(* Logix 5000 project; controller ANG1E_AOI_sample_RSLogix_V31 vendor 1 type 14 code 108 rev 31.11; software revision 31.02 *)

TASK MainTask (continuous, watchdog 500 ms) : MainProgram

MODULES
   Local : vendor 1 type 14 code 108 (Compact 0, rev 31.11)
      AMCI_ANG1E : ETHERNET-MODULE (Ethernet 192.168.0.50, rev 1.1, Output RPI 10 ms)
END_MODULES

TYPE ANG1_Driver_Command :
STRUCT
   Absolute_move : BOOL;
   Relative_move : BOOL;
   Hold_move : BOOL;
   Resume_move : BOOL;
   Immediate_stop : BOOL;
   Find_Home_CW : BOOL;
   Find_Home_CCW : BOOL;
   CW_Manual_Move : BOOL;
   CCW_Manual_Move : BOOL;
   Preset_Motor_Position : BOOL;
   Reset_Errors : BOOL;
   Program_Assembled_Move : BOOL;
   Program_Assembled_Move_segments : BOOL;
   Run_Assembled_Move : BOOL;
   Preset_Encoder : BOOL;
   Mode_bit : BOOL;   // "0"=command mode, "1" = configuraiton mode
   Motor_Current_Key0 : BOOL;
   Motor_Current_Key1 : BOOL;
   Encoder_move : BOOL;
   Reserved_bit_3 : BOOL;
   Blend_Move_Direction : BOOL;
   Reserved_bit_5 : BOOL;
   Enable_Electronic_Gearing : BOOL;
   Reserved_bit_7 : BOOL;
   Reserved_bit_8 : BOOL;
   Reserved_bit_9 : BOOL;
   Reserved_bit_10 : BOOL;
   Home_Proximity_Bit : BOOL;
   Reserved_bit_12 : BOOL;
   General_Purpose_output : BOOL;
   Reserved_bit_14 : BOOL;
   Drive_Enable : BOOL;   // "0" to disable motor current, "1" to enable motor current
   upper_target_position : INT;
   lower_target_position : INT;
   upper_programmed_speed : INT;
   lower_programmed_speed : INT;
   Acceleration : INT;   // 1 to 5000 steps/ms/sec
   Decleration : INT;   // 1 to 5000 steps/ms/sec
   Motor_Current : INT;   // 10 to 40, represents 1.0 to 4.0 amps rms
   acceleration_jerk : INT;   // 0 to 5000
END_STRUCT
END_TYPE

TYPE ANG1_Driver_Configuration :
STRUCT
   Input_1_bit_0 : BOOL;
   Input_1_bit_1 : BOOL;
   Input_1_bit_2 : BOOL;
   Input_2_bit_3 : BOOL;
   Input_2_bit_4 : BOOL;
   Input_2_bit_5 : BOOL;
   Input_3_bit_6 : BOOL;
   Input_3_bit_7 : BOOL;
   Input_3_bit_8 : BOOL;
   Reserved_bit_9 : BOOL;
   Quad_encoder_enable : BOOL;   // "0" when Quadrature Encoder is not used, "1" when Quadrature is used
   Home_Proximity_enable : BOOL;   // "0" when the Home Proximity bit is not used, "1" when the Home Proximity will be used
   Reserved_bit_12 : BOOL;
   Stall_detection_enable : BOOL;   // "0' disables Stall Detection, "1" enables Stall Detection
   Anti_resonance_enable : BOOL;   // "0" Enables Antiresonance, "1" Disables Antiresonance
   Mode_bit : BOOL;   // "1"=configuration mode, "0" = command mode
   Input_1_Active_state : BOOL;   // "0" = normally closed, "1" = normally open
   Input_2_Active_state : BOOL;   // "0" = normally closed, "1" = normally open
   Input_3_Active_state : BOOL;   // "0" = normally closed, "1" = normally open
   Reserved_bit_3 : BOOL;
   Reserved_bit_4 : BOOL;
   Reserved_bit_5 : BOOL;
   Reserved_bit_6 : BOOL;
   Reserved_bit_7 : BOOL;
   Reserved_bit_8 : BOOL;
   _Reserved_bit_9 : BOOL;
   Reserved_bit_10 : BOOL;
   Reserved_bit_11 : BOOL;
   Output_state_when_network_lost : BOOL;
   Program_output_state_when_network_lost : BOOL;
   Output_Functionality : BOOL;   // "0"=Fault Output, "1" = General Purpose Output
   Drive_Enable : BOOL;   // "0"=Disabled, "1"=Enabled
   Upper_Starting_Speed : INT;   // 0 to 999
   Lower_Starting_Speed : INT;   // 0 to 999
   Motor_Steps_Turn : INT;   // 200 to 32767
   Reserved_word_5 : INT;
   Encoder_pulses_turn : INT;   // 0 to 32,768
   Idle_current_percentage : INT;   // 0 to 100%
   Motor_Current_X10 : INT;   // 10 to 40, represents 1.0 to 4.0 amps rms
   Current_loop_gain : INT;   // 1 to 40
END_STRUCT
END_TYPE

ADD_ON_INSTRUCTION AMCI_ANG1E_Absolute_Move   (* revision 6.1, vendor AMCI, ExecuteEnableInFalse *)
// Revision note:
// Version 5.0 added the (hidden) ability to program the motor current and unlatched the error bit if the rung goes false.
// 8/5/2019.  Version 6 automatically issued the reset error command if the move complete bit was set.  This will reset the move complete bit and allow short moves to occur.
// 7/31/23 V6.1 Changed how the AOI EN bit is set.   Instead of when the Move complete bit is not set, it is now set when the move command is issued.
VAR_INPUT
   Axis_Status_Bits : INT; {required}
   slot_axis_number : INT; {required}
   Type_0_for_standard_1_for_indexed : BOOL;
   Target_Position : DINT; {required}
   Programmed_Speed : DINT; {required}
   Acceleration : INT; {required}
   Deceleration : INT; {required}
   motor_current : INT;
   Jerk : INT;
END_VAR
VAR_IN_OUT
   AMCI_ANG1E_output_data : INT[10]; {required}
END_VAR
VAR_OUTPUT
   EN : BOOL; {access Read Only, visible}
   ER : BOOL; {access Read Only, visible}
END_VAR
VAR
   Upper_Result_X_1000 : DINT;
   command_data_block : INT[10];
        [1]   // Command Bits LSW
        [0]   // Command Bits MSW
        [3]   // Lower Target Position
        [2]   // Upper Target Position
        [5]   // Lower Programmed Speed
        [4]   // Upper Programmed Speed
   index : INT;
END_VAR

ROUTINE EnableInFalse   (* ladder *)
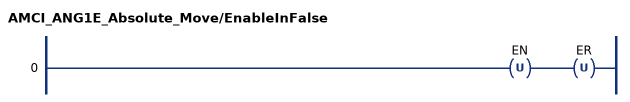
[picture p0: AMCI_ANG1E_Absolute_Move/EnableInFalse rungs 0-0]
   0: OTU(EN)OTU(ER);
END_ROUTINE

ROUTINE Logic   (* ladder *)
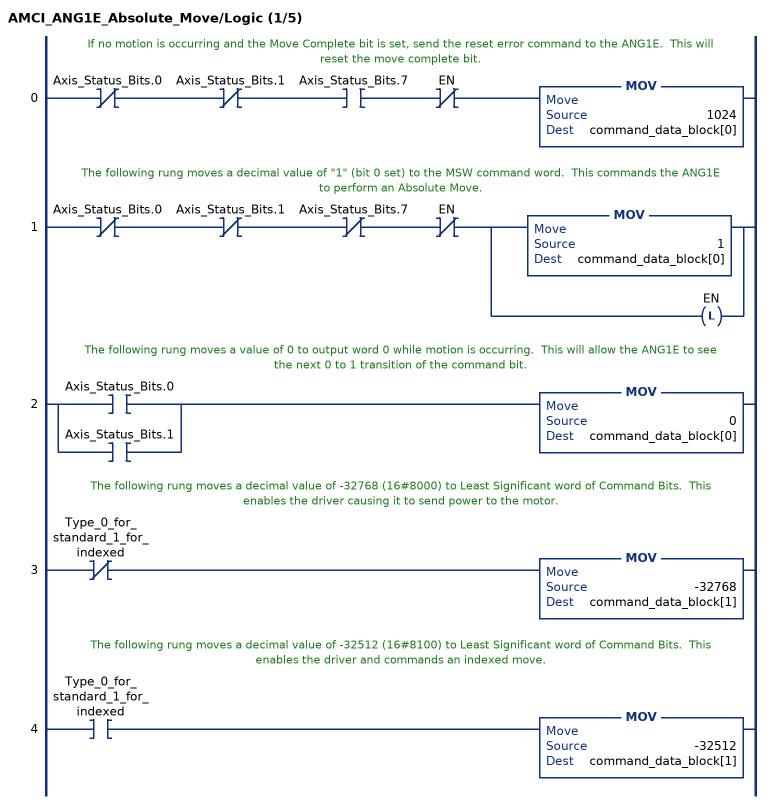
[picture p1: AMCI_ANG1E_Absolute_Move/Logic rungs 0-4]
   // If no motion is occurring and the Move Complete bit is set, send the reset error command to the ANG1E.  This will reset the move complete bit.
   0: XIO(Axis_Status_Bits.0)XIO(Axis_Status_Bits.1)XIC(Axis_Status_Bits.7)XIO(EN)MOV(1024,command_data_block[0]);
   // The following rung moves a decimal value of "1" (bit 0 set) to the MSW command word.  This commands the ANG1E to perform an Absolute Move.
   1: XIO(Axis_Status_Bits.0)XIO(Axis_Status_Bits.1)XIO(Axis_Status_Bits.7)XIO(EN)[MOV(1,command_data_block[0]) ,OTL(EN) ];
   // The following rung moves a value of 0 to output word 0 while motion is occurring.  This will allow the ANG1E to see the next 0 to 1 transition of the command bit.
   2: [XIC(Axis_Status_Bits.0) ,XIC(Axis_Status_Bits.1) ]MOV(0,command_data_block[0]);
   // The following rung moves a decimal value of -32768 (16#8000) to Least Significant word of Command Bits.  This enables the driver causing it to send power to the motor.
   3: XIO(Type_0_for_standard_1_for_indexed)MOV(-32768,command_data_block[1]);
   // The following rung moves a decimal value of -32512 (16#8100) to Least Significant word of Command Bits.  This enables the driver and commands an indexed move.
   4: XIC(Type_0_for_standard_1_for_indexed)MOV(-32512,command_data_block[1]);
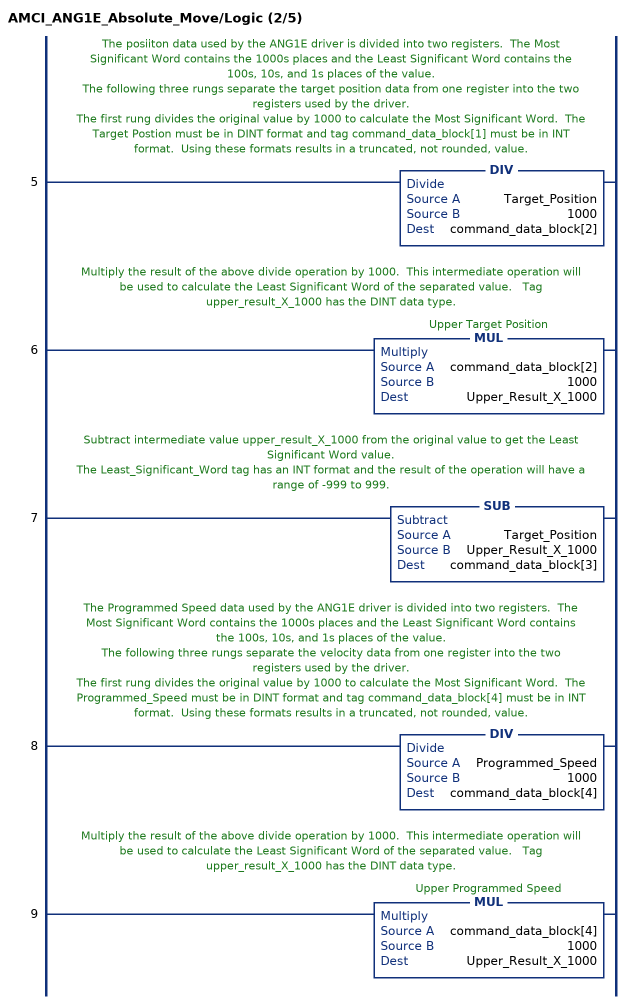
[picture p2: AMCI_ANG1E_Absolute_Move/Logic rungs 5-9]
   // The posiiton data used by the ANG1E driver is divided into two registers.  The Most Significant Word contains the 1000s places and the Least Significant Word contains the 100s, 10s, and 1s places of the value.
   // The following three rungs separate the target position data from one register into the two registers used by the driver.
   // The first rung divides the original value by 1000 to calculate the Most Significant Word.  The Target Postion must be in DINT format and tag command_data_block[1] must be in INT format.  Using these formats results in a truncated, not rounded, value.
   5: DIV(Target_Position,1000,command_data_block[2]);
   // Multiply the result of the above divide operation by 1000.  This intermediate operation will be used to calculate the Least Significant Word of the separated value.   Tag upper_result_X_1000 has the DINT data type.
   6: MUL(command_data_block[2],1000,Upper_Result_X_1000);
   // Subtract intermediate value upper_result_X_1000 from the original value to get the Least Significant Word value.
   // The Least_Significant_Word tag has an INT format and the result of the operation will have a range of -999 to 999.
   7: SUB(Target_Position,Upper_Result_X_1000,command_data_block[3]);
   // The Programmed Speed data used by the ANG1E driver is divided into two registers.  The Most Significant Word contains the 1000s places and the Least Significant Word contains the 100s, 10s, and 1s places of the value.
   // The following three rungs separate the velocity data from one register into the two registers used by the driver.
   // The first rung divides the original value by 1000 to calculate the Most Significant Word.  The Programmed_Speed must be in DINT format and tag command_data_block[4] must be in INT format.  Using these formats results in a truncated, not rounded, value.
   8: DIV(Programmed_Speed,1000,command_data_block[4]);
   // Multiply the result of the above divide operation by 1000.  This intermediate operation will be used to calculate the Least Significant Word of the separated value.   Tag upper_result_X_1000 has the DINT data type.
   9: MUL(command_data_block[4],1000,Upper_Result_X_1000);
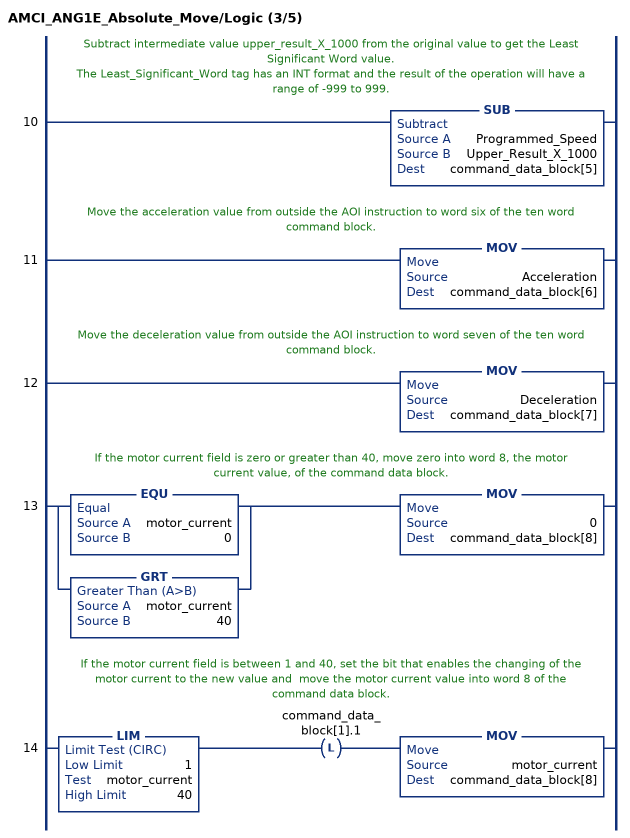
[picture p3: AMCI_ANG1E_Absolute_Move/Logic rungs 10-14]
   // Subtract intermediate value upper_result_X_1000 from the original value to get the Least Significant Word value.
   // The Least_Significant_Word tag has an INT format and the result of the operation will have a range of -999 to 999.
   10: SUB(Programmed_Speed,Upper_Result_X_1000,command_data_block[5]);
   // Move the acceleration value from outside the AOI instruction to word six of the ten word command block.
   11: MOV(Acceleration,command_data_block[6]);
   // Move the deceleration value from outside the AOI instruction to word seven of the ten word command block.
   12: MOV(Deceleration,command_data_block[7]);
   // If the motor current field is zero or greater than 40, move zero into word 8, the motor current value, of the command data block.
   13: [EQU(motor_current,0) ,GRT(motor_current,40) ]MOV(0,command_data_block[8]);
   // If the motor current field is between 1 and 40, set the bit that enables the changing of the motor current to the new value and  move the motor current value into word 8 of the command data block.
   14: LIM(1,motor_current,40)OTL(command_data_block[1].1)MOV(motor_current,command_data_block[8]);
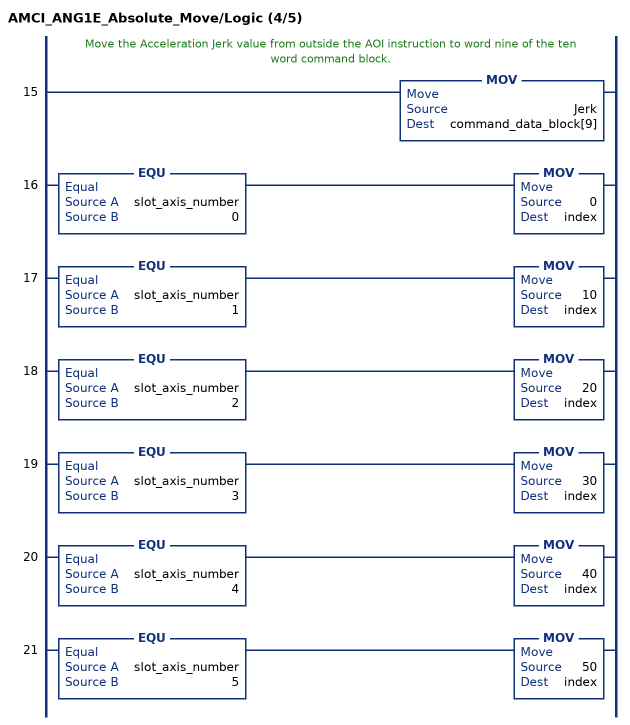
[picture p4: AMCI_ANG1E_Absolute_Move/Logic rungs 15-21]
   // Move the Acceleration Jerk value from outside the AOI instruction to word nine of the ten word command block.
   15: MOV(Jerk,command_data_block[9]);
   16: EQU(slot_axis_number,0)MOV(0,index);
   17: EQU(slot_axis_number,1)MOV(10,index);
   18: EQU(slot_axis_number,2)MOV(20,index);
   19: EQU(slot_axis_number,3)MOV(30,index);
   20: EQU(slot_axis_number,4)MOV(40,index);
   21: EQU(slot_axis_number,5)MOV(50,index);
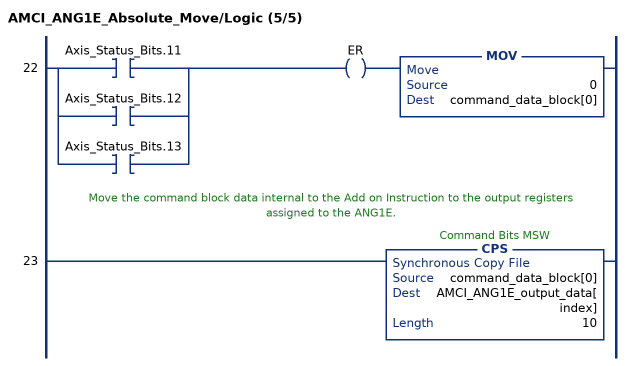
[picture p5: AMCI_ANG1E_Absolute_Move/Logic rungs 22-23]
   22: [XIC(Axis_Status_Bits.11) ,XIC(Axis_Status_Bits.12) ,XIC(Axis_Status_Bits.13) ]OTE(ER)MOV(0,command_data_block[0]);
   // Move the command block data internal to the Add on Instruction to the output registers assigned to the ANG1E.
   23: CPS(command_data_block[0],AMCI_ANG1E_output_data[index],10);
END_ROUTINE
END_ADD_ON_INSTRUCTION

ADD_ON_INSTRUCTION AMCI_ANG1E_Configure   (* revision 1.0 *)
VAR_INPUT
   slot_axis_number : INT; {required}   // 0=all switches off 1=switch 1 on 2=switch 2 on 3=switch 3 on 4=switch 4 on 5=swich 5 on
   Input_1_Function : INT; {required}
   Input_1_Active_State : BOOL; {required}
   Input_2_Function : INT; {required}
   Input_2_Active_State : BOOL; {required}
   Input_3_Function : INT; {required}
   Input_3_Active_State : BOOL; {required}
   Z_Input_Home : BOOL;
   Encoder_Enable : BOOL; {required}
   Backplane_Home_Proximity_Enable : BOOL;
   Stall_Detect_Enable : BOOL;
   Antiresonance : BOOL;
   Input_Data_Format_0_standard_1_binary : BOOL;
   Output_State_Network_Lost : BOOL;
   Output_Control_Network_Lost : BOOL;
   Output_Functionality : BOOL;
   Drive_Enable : BOOL := 1;
   Starting_Speed : DINT; {required}
   Motor_Steps_Turn : INT; {required}
   Encoder_Counts_Turn : INT; {required}
   Idle_Current : INT; {required}
   Motor_Current : INT; {required}
   Current_Loop_Gain : INT; {required}
END_VAR
VAR_IN_OUT
   AMCI_ANG1E_Output_data : INT[10]; {required}
END_VAR
VAR
   upper_result_X_1000 : DINT;
   command_data_block : INT[10];
        [0].15   // Mode Bit 1=Configuraiton Mode 0=Command Mode
   index : INT;
END_VAR

ROUTINE Logic   (* ladder *)
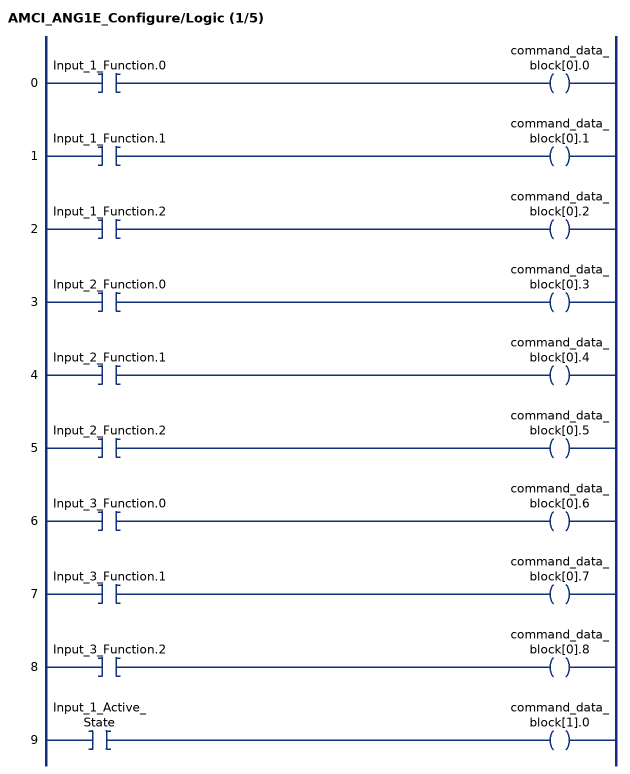
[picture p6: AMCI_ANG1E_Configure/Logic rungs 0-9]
   0: XIC(Input_1_Function.0)OTE(command_data_block[0].0);
   1: XIC(Input_1_Function.1)OTE(command_data_block[0].1);
   2: XIC(Input_1_Function.2)OTE(command_data_block[0].2);
   3: XIC(Input_2_Function.0)OTE(command_data_block[0].3);
   4: XIC(Input_2_Function.1)OTE(command_data_block[0].4);
   5: XIC(Input_2_Function.2)OTE(command_data_block[0].5);
   6: XIC(Input_3_Function.0)OTE(command_data_block[0].6);
   7: XIC(Input_3_Function.1)OTE(command_data_block[0].7);
   8: XIC(Input_3_Function.2)OTE(command_data_block[0].8);
   9: XIC(Input_1_Active_State)OTE(command_data_block[1].0);
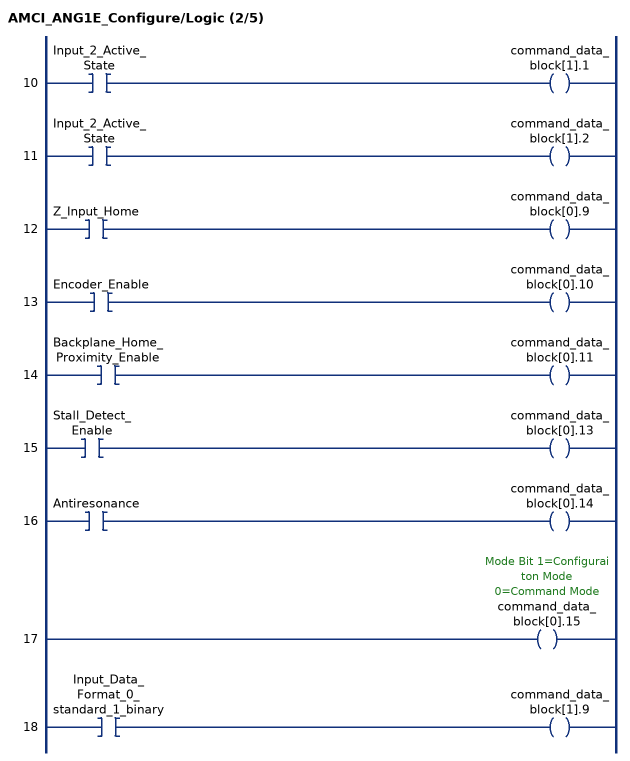
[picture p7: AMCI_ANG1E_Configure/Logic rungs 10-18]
   10: XIC(Input_2_Active_State)OTE(command_data_block[1].1);
   11: XIC(Input_2_Active_State)OTE(command_data_block[1].2);
   12: XIC(Z_Input_Home)OTE(command_data_block[0].9);
   13: XIC(Encoder_Enable)OTE(command_data_block[0].10);
   14: XIC(Backplane_Home_Proximity_Enable)OTE(command_data_block[0].11);
   15: XIC(Stall_Detect_Enable)OTE(command_data_block[0].13);
   16: XIC(Antiresonance)OTE(command_data_block[0].14);
   17: OTE(command_data_block[0].15);
   18: XIC(Input_Data_Format_0_standard_1_binary)OTE(command_data_block[1].9);
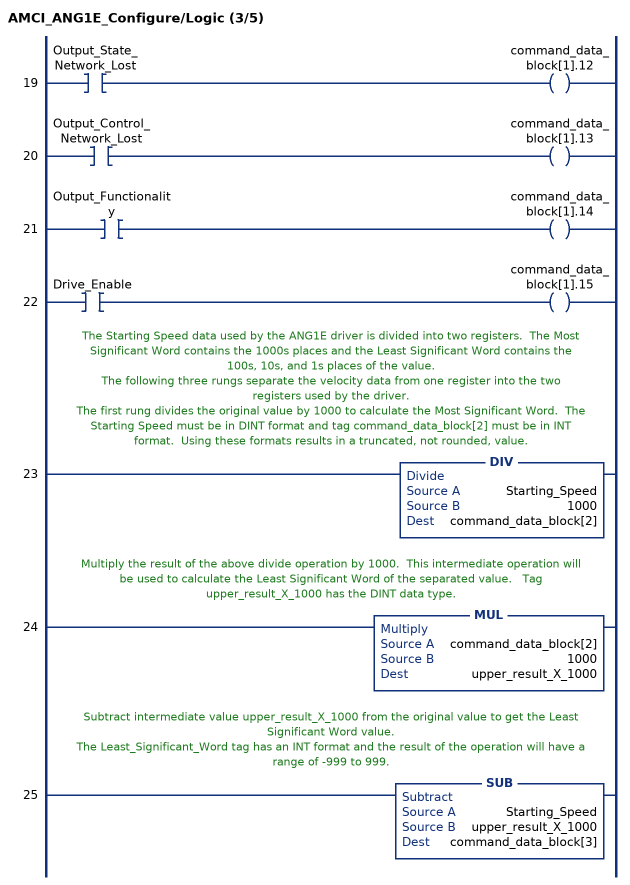
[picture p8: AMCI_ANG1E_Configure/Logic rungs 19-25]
   19: XIC(Output_State_Network_Lost)OTE(command_data_block[1].12);
   20: XIC(Output_Control_Network_Lost)OTE(command_data_block[1].13);
   21: XIC(Output_Functionality)OTE(command_data_block[1].14);
   22: XIC(Drive_Enable)OTE(command_data_block[1].15);
   // The Starting Speed data used by the ANG1E driver is divided into two registers.  The Most Significant Word contains the 1000s places and the Least Significant Word contains the 100s, 10s, and 1s places of the value.
   // The following three rungs separate the velocity data from one register into the two registers used by the driver.
   // The first rung divides the original value by 1000 to calculate the Most Significant Word.  The Starting Speed must be in DINT format and tag command_data_block[2] must be in INT format.  Using these formats results in a truncated, not rounded, value.
   23: DIV(Starting_Speed,1000,command_data_block[2]);
   // Multiply the result of the above divide operation by 1000.  This intermediate operation will be used to calculate the Least Significant Word of the separated value.   Tag upper_result_X_1000 has the DINT data type.
   24: MUL(command_data_block[2],1000,upper_result_X_1000);
   // Subtract intermediate value upper_result_X_1000 from the original value to get the Least Significant Word value.
   // The Least_Significant_Word tag has an INT format and the result of the operation will have a range of -999 to 999.
   25: SUB(Starting_Speed,upper_result_X_1000,command_data_block[3]);
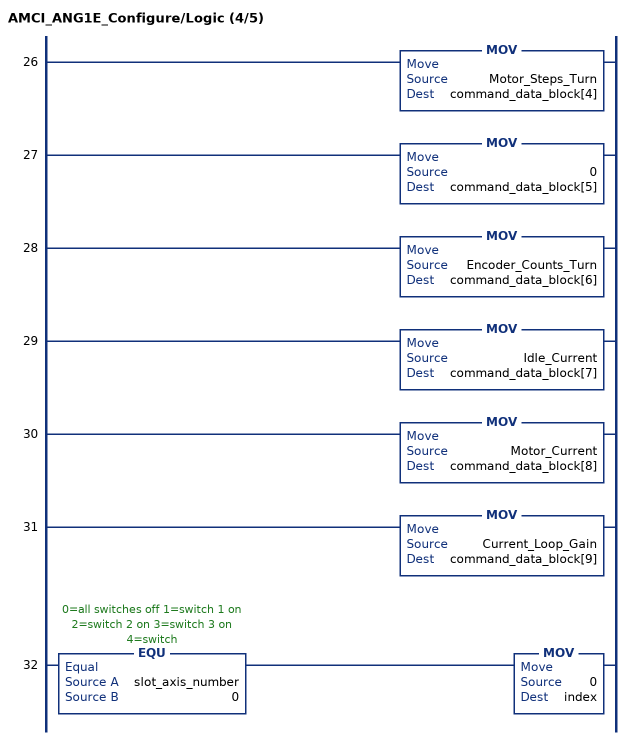
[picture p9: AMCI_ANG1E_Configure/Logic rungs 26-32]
   26: MOV(Motor_Steps_Turn,command_data_block[4]);
   27: MOV(0,command_data_block[5]);
   28: MOV(Encoder_Counts_Turn,command_data_block[6]);
   29: MOV(Idle_Current,command_data_block[7]);
   30: MOV(Motor_Current,command_data_block[8]);
   31: MOV(Current_Loop_Gain,command_data_block[9]);
   32: EQU(slot_axis_number,0)MOV(0,index);
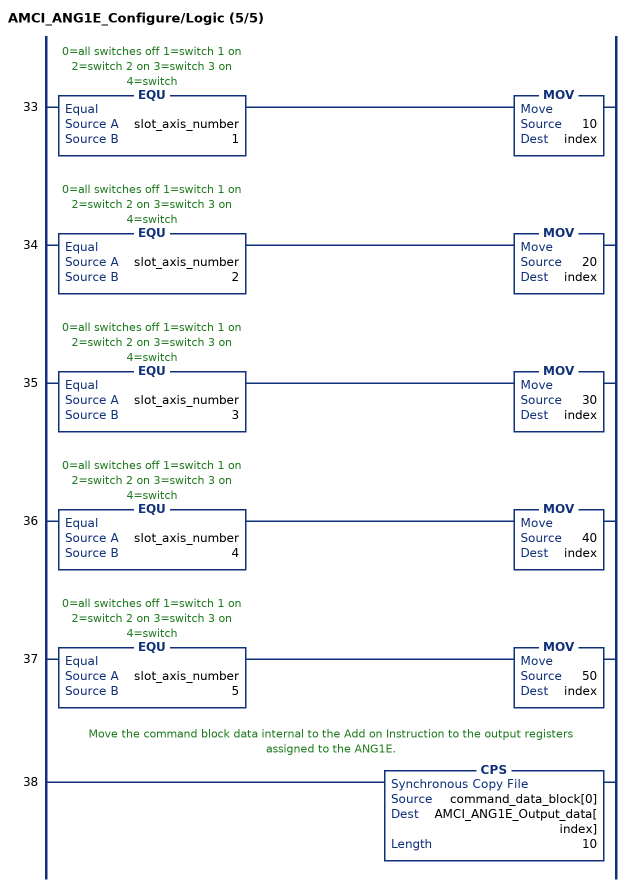
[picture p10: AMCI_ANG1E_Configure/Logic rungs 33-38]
   33: EQU(slot_axis_number,1)MOV(10,index);
   34: EQU(slot_axis_number,2)MOV(20,index);
   35: EQU(slot_axis_number,3)MOV(30,index);
   36: EQU(slot_axis_number,4)MOV(40,index);
   37: EQU(slot_axis_number,5)MOV(50,index);
   // Move the command block data internal to the Add on Instruction to the output registers assigned to the ANG1E.
   38: CPS(command_data_block[0],AMCI_ANG1E_Output_data[index],10);
END_ROUTINE
END_ADD_ON_INSTRUCTION

ADD_ON_INSTRUCTION AMCI_ANG1E_Disable_Driver   (* revision 1.1, vendor AMCI *)
// Revision note:
// Version 1.1 added the slot_axis number and the input parameters can now be tags or discrete values.
VAR_INPUT
   slot_axis_number : INT; {required}
END_VAR
VAR_IN_OUT
   AMCI_ANG1E_output_data : INT[10]; {required}
END_VAR
VAR
   command_data_block : INT[10];
        [1]   // Command Bits LSW
        [3]   // Lower Target Position
        [5]   // Lower Programmed Speed
        [0]   // Command Bits MSW
        [2]   // Upper Target Position
        [4]   // Upper Programmed Speed
   index : INT;
END_VAR

ROUTINE Logic   (* ladder *)
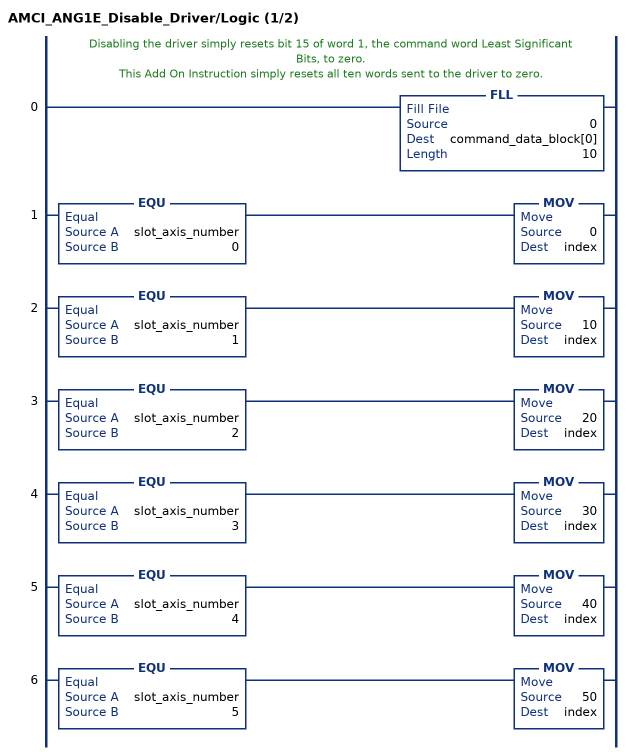
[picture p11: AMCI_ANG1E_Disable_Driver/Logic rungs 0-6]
   // Disabling the driver simply resets bit 15 of word 1, the command word Least Significant Bits, to zero.
   // This Add On Instruction simply resets all ten words sent to the driver to zero.
   0: FLL(0,command_data_block[0],10);
   1: EQU(slot_axis_number,0)MOV(0,index);
   2: EQU(slot_axis_number,1)MOV(10,index);
   3: EQU(slot_axis_number,2)MOV(20,index);
   4: EQU(slot_axis_number,3)MOV(30,index);
   5: EQU(slot_axis_number,4)MOV(40,index);
   6: EQU(slot_axis_number,5)MOV(50,index);
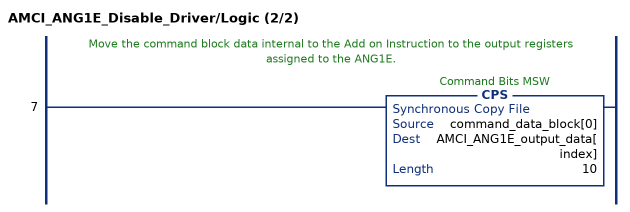
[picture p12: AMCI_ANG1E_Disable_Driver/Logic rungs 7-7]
   // Move the command block data internal to the Add on Instruction to the output registers assigned to the ANG1E.
   7: CPS(command_data_block[0],AMCI_ANG1E_output_data[index],10);
END_ROUTINE
END_ADD_ON_INSTRUCTION

ADD_ON_INSTRUCTION AMCI_ANG1E_Enable_Driver   (* revision 1.1, vendor AMCI *)
// Revision note:
// Version 1.1 added the slot_axis number and the input parameters can now be tags or discrete values.
VAR_INPUT
   slot_axis_number : INT; {required}
END_VAR
VAR_IN_OUT
   AMCI_ANG1E_output_data : INT[10]; {required}
END_VAR
VAR
   command_data_block : INT[10];
        [1]   // Command Bits LSW
        [3]   // Lower Target Position
        [5]   // Lower Programmed Speed
        [0]   // Command Bits MSW
        [2]   // Upper Target Position
        [4]   // Upper Programmed Speed
   index : INT;
END_VAR

ROUTINE Logic   (* ladder *)
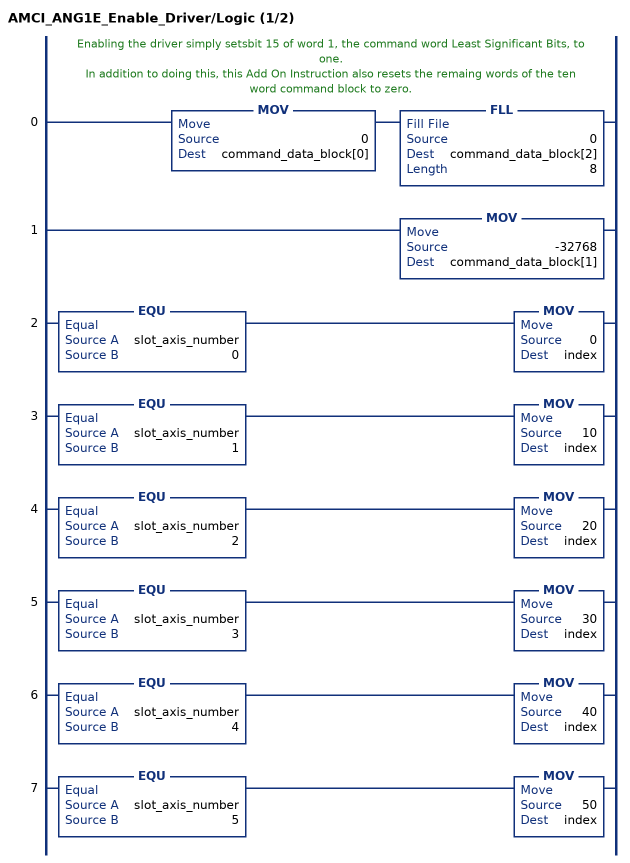
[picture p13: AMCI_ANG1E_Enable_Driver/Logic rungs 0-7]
   // Enabling the driver simply setsbit 15 of word 1, the command word Least Significant Bits, to one.
   // In addition to doing this, this Add On Instruction also resets the remaing words of the ten word command block to zero.
   0: MOV(0,command_data_block[0])FLL(0,command_data_block[2],8);
   1: MOV(-32768,command_data_block[1]);
   2: EQU(slot_axis_number,0)MOV(0,index);
   3: EQU(slot_axis_number,1)MOV(10,index);
   4: EQU(slot_axis_number,2)MOV(20,index);
   5: EQU(slot_axis_number,3)MOV(30,index);
   6: EQU(slot_axis_number,4)MOV(40,index);
   7: EQU(slot_axis_number,5)MOV(50,index);
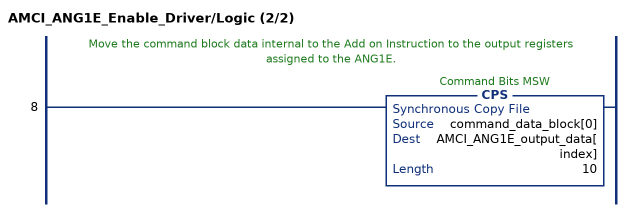
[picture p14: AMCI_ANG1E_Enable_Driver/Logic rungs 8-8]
   // Move the command block data internal to the Add on Instruction to the output registers assigned to the ANG1E.
   8: CPS(command_data_block[0],AMCI_ANG1E_output_data[index],10);
END_ROUTINE
END_ADD_ON_INSTRUCTION

ADD_ON_INSTRUCTION AMCI_ANG1E_Encoder_Follower   (* revision 5.0, vendor AMCI, ExecuteEnableInFalse *)
// Revision note:
// Version 5.0 added the (hidden) ability to program the motor current and unlatched the error bit if the rung goes false.
VAR_INPUT
   Axis_Status_Bits : INT; {required}
   slot_axis_number : INT; {required}
   Electronic_Gearing_Numerator : INT; {required}
   Electronic_Gearing_Denominator : INT; {required}
   Programmed_Speed : DINT; {required}
   Acceleration : INT; {required}
   Deceleration : INT; {required}
   motor_current : INT;
   jerk : INT;
END_VAR
VAR_IN_OUT
   AMCI_ANG1E_output_data : INT[10]; {required}
END_VAR
VAR_OUTPUT
   EN : BOOL; {access Read Only, visible}
   Encoder_Follower_Occurring : BOOL; {access Read Only, visible}
   ER : BOOL; {access Read Only, visible}
END_VAR
VAR
   Upper_Result_X_1000 : DINT;
   command_data_block : INT[10];
        [1]   // Command Bits LSW
        [0]   // Command Bits MSW
        [5]   // Lower Programmed Speed
        [4]   // Upper Programmed Speed
   index : INT;
END_VAR

ROUTINE EnableInFalse   (* ladder *)
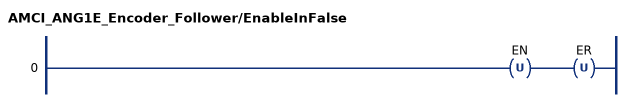
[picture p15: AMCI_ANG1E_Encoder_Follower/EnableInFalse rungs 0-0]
   0: OTU(EN)OTU(ER);
END_ROUTINE

ROUTINE Logic   (* ladder *)
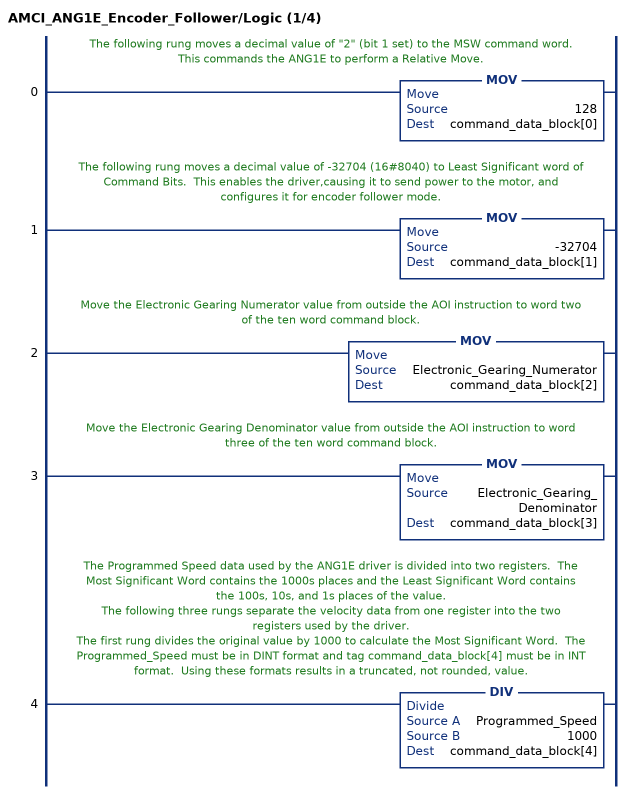
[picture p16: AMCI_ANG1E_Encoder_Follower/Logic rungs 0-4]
   // The following rung moves a decimal value of "2" (bit 1 set) to the MSW command word.  This commands the ANG1E to perform a Relative Move.
   0: MOV(128,command_data_block[0]);
   // The following rung moves a decimal value of -32704 (16#8040) to Least Significant word of Command Bits.  This enables the driver,causing it to send power to the motor, and configures it for encoder follower mode.
   1: MOV(-32704,command_data_block[1]);
   // Move the Electronic Gearing Numerator value from outside the AOI instruction to word two of the ten word command block.
   2: MOV(Electronic_Gearing_Numerator,command_data_block[2]);
   // Move the Electronic Gearing Denominator value from outside the AOI instruction to word three of the ten word command block.
   3: MOV(Electronic_Gearing_Denominator,command_data_block[3]);
   // The Programmed Speed data used by the ANG1E driver is divided into two registers.  The Most Significant Word contains the 1000s places and the Least Significant Word contains the 100s, 10s, and 1s places of the value.
   // The following three rungs separate the velocity data from one register into the two registers used by the driver.
   // The first rung divides the original value by 1000 to calculate the Most Significant Word.  The Programmed_Speed must be in DINT format and tag command_data_block[4] must be in INT format.  Using these formats results in a truncated, not rounded, value.
   4: DIV(Programmed_Speed,1000,command_data_block[4]);
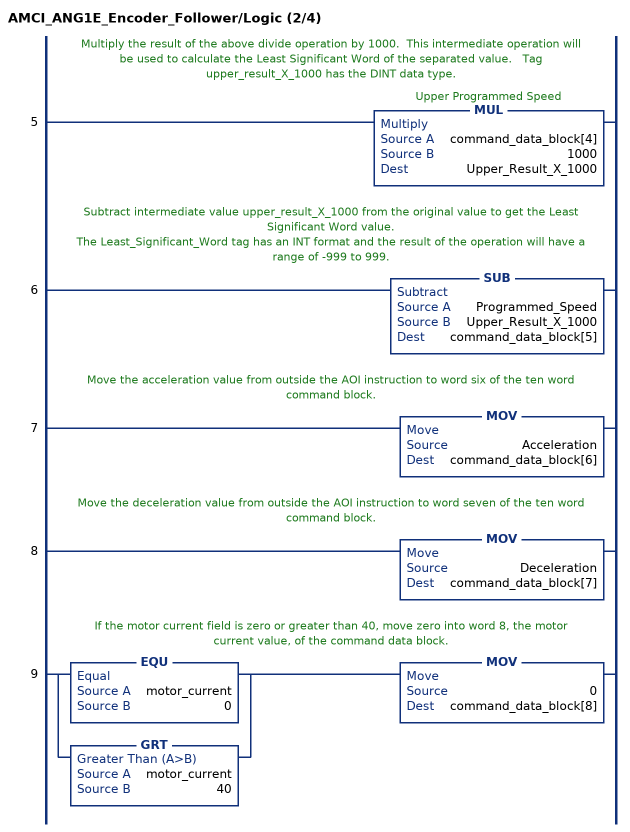
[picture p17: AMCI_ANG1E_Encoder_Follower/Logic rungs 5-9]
   // Multiply the result of the above divide operation by 1000.  This intermediate operation will be used to calculate the Least Significant Word of the separated value.   Tag upper_result_X_1000 has the DINT data type.
   5: MUL(command_data_block[4],1000,Upper_Result_X_1000);
   // Subtract intermediate value upper_result_X_1000 from the original value to get the Least Significant Word value.
   // The Least_Significant_Word tag has an INT format and the result of the operation will have a range of -999 to 999.
   6: SUB(Programmed_Speed,Upper_Result_X_1000,command_data_block[5]);
   // Move the acceleration value from outside the AOI instruction to word six of the ten word command block.
   7: MOV(Acceleration,command_data_block[6]);
   // Move the deceleration value from outside the AOI instruction to word seven of the ten word command block.
   8: MOV(Deceleration,command_data_block[7]);
   // If the motor current field is zero or greater than 40, move zero into word 8, the motor current value, of the command data block.
   9: [EQU(motor_current,0) ,GRT(motor_current,40) ]MOV(0,command_data_block[8]);
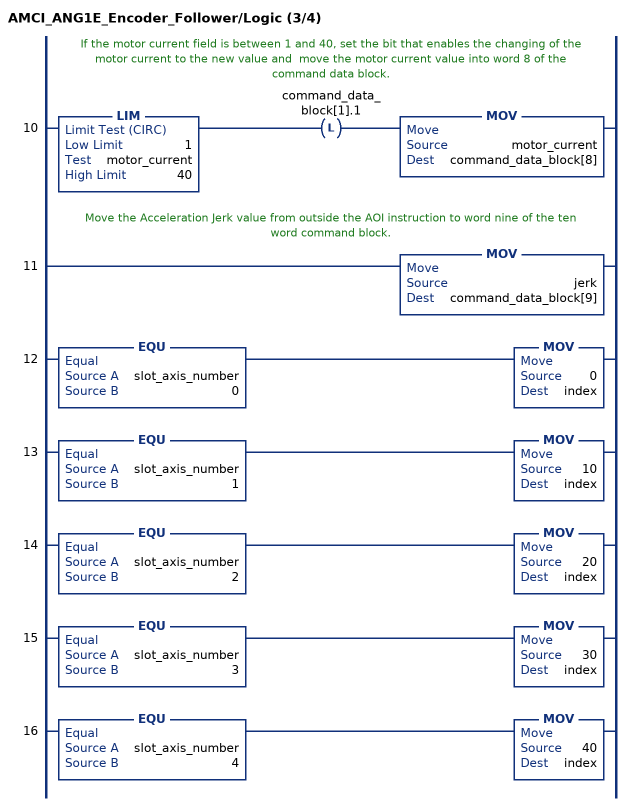
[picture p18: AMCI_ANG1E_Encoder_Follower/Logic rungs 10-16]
   // If the motor current field is between 1 and 40, set the bit that enables the changing of the motor current to the new value and  move the motor current value into word 8 of the command data block.
   10: LIM(1,motor_current,40)OTL(command_data_block[1].1)MOV(motor_current,command_data_block[8]);
   // Move the Acceleration Jerk value from outside the AOI instruction to word nine of the ten word command block.
   11: MOV(jerk,command_data_block[9]);
   12: EQU(slot_axis_number,0)MOV(0,index);
   13: EQU(slot_axis_number,1)MOV(10,index);
   14: EQU(slot_axis_number,2)MOV(20,index);
   15: EQU(slot_axis_number,3)MOV(30,index);
   16: EQU(slot_axis_number,4)MOV(40,index);
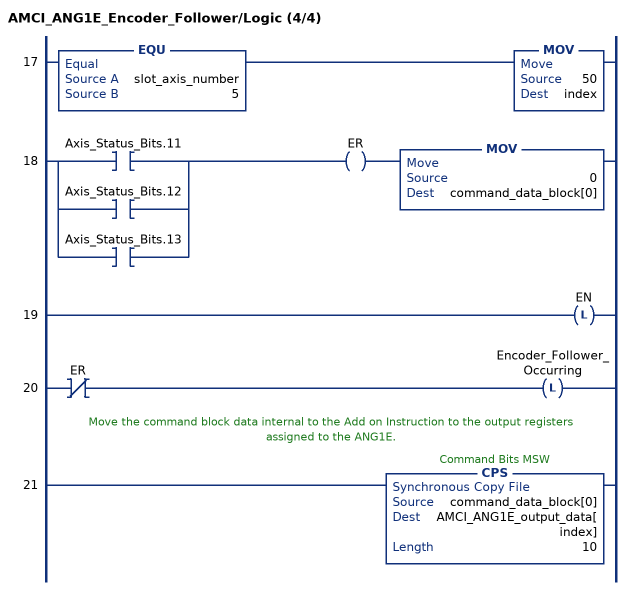
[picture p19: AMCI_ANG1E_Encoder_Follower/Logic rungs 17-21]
   17: EQU(slot_axis_number,5)MOV(50,index);
   18: [XIC(Axis_Status_Bits.11) ,XIC(Axis_Status_Bits.12) ,XIC(Axis_Status_Bits.13) ]OTE(ER)MOV(0,command_data_block[0]);
   19: OTL(EN);
   20: XIO(ER)OTL(Encoder_Follower_Occurring);
   // Move the command block data internal to the Add on Instruction to the output registers assigned to the ANG1E.
   21: CPS(command_data_block[0],AMCI_ANG1E_output_data[index],10);
END_ROUTINE
END_ADD_ON_INSTRUCTION
